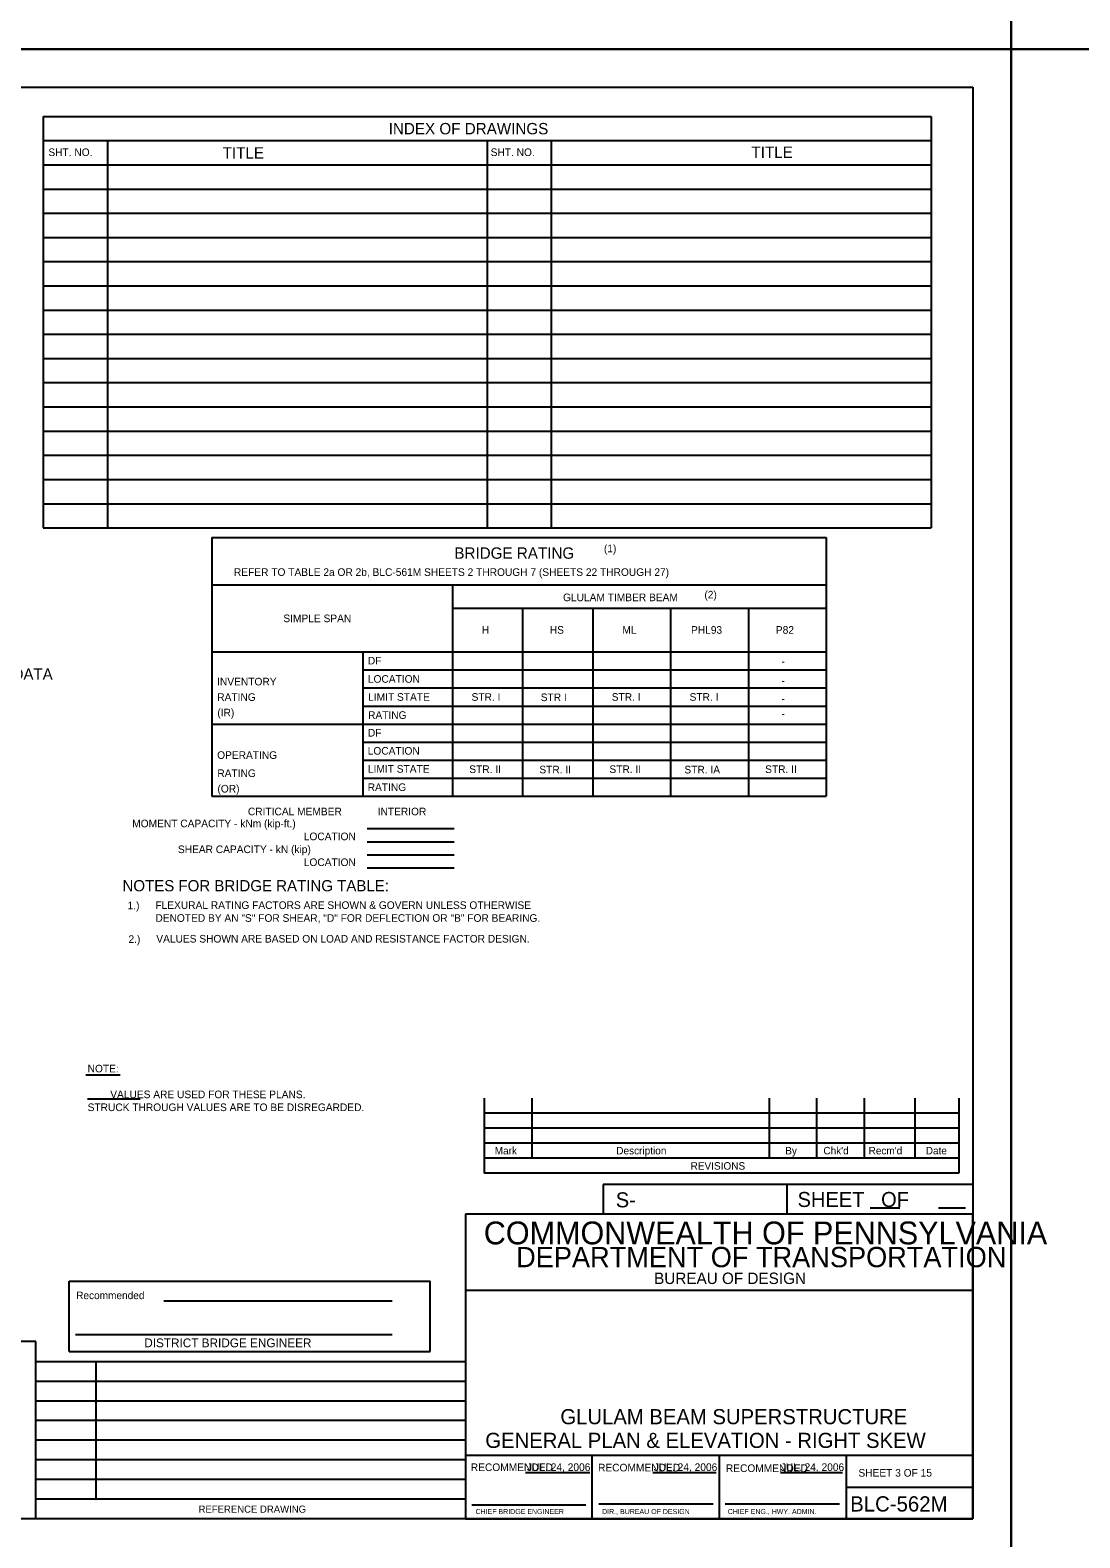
# Model space of a CAD drawing. Extents: x 638263 to 640360, y 293683 to 298655.
# Drawn here: x 638890 to 639304, y 296661 to 297255 of the extents above; entities that cross this region are included whole.
import ezdxf

# ---------------------------------------------------------------- set-up
doc = ezdxf.new("R2010")
doc.units = 0
for name, color, linetype in [('2', 7, 'Continuous'), ('4', 7, 'Continuous'), ('7', 7, 'Continuous'), ('PLT-BNDY', 7, 'Continuous')]:
    doc.layers.add(name, color=color, linetype=linetype)

msp = doc.modelspace()

# ---------------------------------------------------------------- linework, layer by layer
at = {"layer": '2'}
for p, q in [((638475.46, 297232.46), (639261.46, 297232.46)), ((639261.46, 297232.46), (639261.46, 296668.46)), ((638911.89, 296843.36), (638925.46, 296843.36)), ((638912.63, 296833.92), (638933.33, 296833.92)), ((639068.92, 296834.15), (639068.92, 296804.62)), ((639087.62, 296834.15), (639087.62, 296810.53)), ((639181.13, 296834.15), (639181.13, 296810.53)), ((639199.83, 296834.15), (639199.83, 296810.53)), ((639218.53, 296834.15), (639218.53, 296810.53)), ((639238.59, 296834.15), (639238.59, 296810.53)), ((639255.94, 296834.15), (639255.94, 296804.62)), ((639255.94, 296828.24), (639068.92, 296828.24)), ((639255.94, 296822.34), (639068.92, 296822.34)), ((639255.94, 296816.43), (639068.92, 296816.43)), ((639255.94, 296810.53), (639068.92, 296810.53)), ((639255.94, 296804.62), (639068.92, 296804.62)), ((639261.46, 296800.11), (639115.78, 296800.11)), ((639115.78, 296800.11), (639115.78, 296788.46)), ((639188.09, 296800.11), (639188.09, 296788.46)), ((639261.46, 296788.46), (639061.46, 296788.46)), ((639061.46, 296788.46), (639061.46, 296668.46)), ((639220.95, 296791), (639232.6, 296791)), ((639247.83, 296791), (639258.56, 296791)), ((639261.46, 296668.46), (639261.46, 296788.46)), ((638905.4, 296734.31), (638905.4, 296762.1)), ((638905.4, 296762.1), (639047.58, 296762.1)), ((639047.58, 296734.31), (639047.58, 296762.1)), ((639261.46, 296758.46), (639061.46, 296758.46)), ((638942.6, 296754.38), (639032.62, 296754.38)), ((638907.84, 296741.02), (639032.62, 296741.02)), ((638905.4, 296734.31), (639047.58, 296734.31)), ((639261.46, 296693.46), (639061.46, 296693.46)), ((639111.46, 296668.46), (639111.46, 296693.46)), ((639161.46, 296693.46), (639161.46, 296668.46)), ((639211.46, 296693.46), (639211.46, 296668.46)), ((639085.11, 296686.64), (639110.49, 296686.64)), ((639135.38, 296686.64), (639160.27, 296686.64)), ((639185.65, 296686.64), (639210.06, 296686.64)), ((639211.46, 296680.96), (639261.46, 296680.96)), ((639063.96, 296673.96), (639108.96, 296673.96)), ((639114.08, 296674.33), (639159.08, 296674.33)), ((639163.83, 296674.33), (639208.83, 296674.33)), ((639261.46, 296668.46), (638475.46, 296668.46)), ((639061.46, 296668.46), (639261.46, 296668.46))]:
    msp.add_line(p, q, dxfattribs=at)
at = {"layer": '4'}
for p, q in [((638895.05, 297220.97), (639245.05, 297220.97)), ((638895.05, 297220.97), (638895.05, 297058.86)), ((639245.05, 297220.97), (639245.05, 297058.86)), ((638895.05, 297211.44), (639070.05, 297211.44)), ((638920.52, 297211.44), (638920.52, 297058.86)), ((639070.05, 297211.44), (639245.05, 297211.44)), ((639070.05, 297211.44), (639070.05, 297058.86)), ((639095.21, 297211.44), (639095.21, 297058.86)), ((638895.05, 297201.9), (639070.05, 297201.9)), ((639070.05, 297201.9), (639245.05, 297201.9)), ((638895.05, 297192.36), (639070.05, 297192.36)), ((639070.05, 297192.36), (639245.05, 297192.36)), ((638895.05, 297182.83), (639070.05, 297182.83)), ((639070.05, 297182.83), (639245.05, 297182.83)), ((638895.05, 297173.29), (639070.05, 297173.29)), ((639070.05, 297173.29), (639245.05, 297173.29)), ((638895.05, 297163.76), (639070.05, 297163.76)), ((639070.05, 297163.76), (639245.05, 297163.76)), ((638895.05, 297154.22), (639070.05, 297154.22)), ((639070.05, 297154.22), (639245.05, 297154.22)), ((638895.05, 297144.68), (639070.05, 297144.68)), ((639070.05, 297144.68), (639245.05, 297144.68)), ((638895.05, 297135.15), (639070.05, 297135.15)), ((639070.05, 297135.15), (639245.05, 297135.15)), ((638895.05, 297125.61), (639070.05, 297125.61)), ((639070.05, 297125.61), (639245.05, 297125.61)), ((638895.05, 297116.08), (639070.05, 297116.08)), ((639070.05, 297116.08), (639245.05, 297116.08)), ((638895.05, 297106.54), (639070.05, 297106.54)), ((639070.05, 297106.54), (639245.05, 297106.54)), ((638895.05, 297097.01), (639070.05, 297097.01)), ((639070.05, 297097.01), (639245.05, 297097.01)), ((638895.05, 297087.47), (639070.05, 297087.47)), ((639070.05, 297087.47), (639245.05, 297087.47)), ((638895.05, 297077.93), (639070.05, 297077.93)), ((639070.05, 297077.93), (639245.05, 297077.93)), ((638895.05, 297068.4), (639070.05, 297068.4)), ((639070.05, 297068.4), (639245.05, 297068.4)), ((638895.05, 297058.86), (639245.05, 297058.86)), ((639021.04, 297002.91), (639203.67, 297002.91)), ((639021.04, 296995.8), (639203.67, 296995.8)), ((639021.04, 296988.68), (639203.67, 296988.68)), ((639021.04, 296974.45), (639203.67, 296974.45)), ((639021.04, 296967.33), (639203.67, 296967.33)), ((639021.04, 296960.22), (639203.67, 296960.22)), ((639022.83, 296940.43), (639057.1, 296940.43)), ((639022.83, 296935.11), (639057.1, 296935.11)), ((639022.83, 296930.06), (639057.1, 296930.06)), ((639022.83, 296924.88), (639057.1, 296924.88)), ((638892.25, 296738.31), (638754.05, 296738.31)), ((638892.25, 296668.46), (638892.25, 296738.31)), ((639061.46, 296730.34), (638892.25, 296730.34)), ((638915.96, 296676.19), (638915.96, 296730.34)), ((639061.46, 296722.6), (638892.25, 296722.6)), ((639061.46, 296714.87), (638892.25, 296714.87)), ((639061.46, 296707.13), (638892.25, 296707.13)), ((639061.46, 296699.4), (638892.25, 296699.4)), ((639061.46, 296691.66), (638892.25, 296691.66)), ((639061.46, 296683.93), (638892.25, 296683.93)), ((639061.46, 296676.19), (638892.25, 296676.19))]:
    msp.add_line(p, q, dxfattribs=at)
at = {"layer": '7'}
for p, q in [((638961.55, 297055.11), (638961.55, 296953.1)), ((638961.55, 297055.11), (639203.67, 297055.11)), ((639203.67, 297055.11), (639203.67, 296953.1)), ((638961.55, 297036.41), (639203.67, 297036.41)), ((639056.4, 297036.41), (639056.4, 296953.1)), ((639056.4, 297027.21), (639203.67, 297027.21)), ((639084.01, 297027.21), (639084.01, 296953.1)), ((639111.62, 297027.21), (639111.62, 296953.1)), ((639142.31, 297027.21), (639142.31, 296953.1)), ((639172.99, 297027.21), (639172.99, 296953.1)), ((638961.55, 297010.03), (639203.67, 297010.03)), ((639021.04, 297010.03), (639021.04, 296953.1)), ((638961.55, 296981.56), (639203.67, 296981.56)), ((638961.55, 296953.1), (639203.67, 296953.1))]:
    msp.add_line(p, q, dxfattribs=at)
at = {"layer": 'PLT-BNDY'}
for points in [[(638435.46, 297841.46), (639276.46, 297841.46), (639276.46, 297247.46), (638435.46, 297247.46)], [(639276.46, 297841.46), (640117.46, 297841.46), (640117.46, 297247.46), (639276.46, 297247.46)], [(638435.46, 297247.46), (639276.46, 297247.46), (639276.46, 296653.46), (638435.46, 296653.46)], [(639276.46, 297247.46), (640117.46, 297247.46), (640117.46, 296653.46), (639276.46, 296653.46)]]:
    msp.add_lwpolyline(points, close=True, dxfattribs=at)

# ---------------------------------------------------------------- texts
at = {"layer": '2'}
for s, height, p in [('MOMENT CAPACITY - kNm (kip-ft.)', 3, (638930.2, 296940.9)), ('LOCATION', 3, (638997.8, 296935.81)), ('SHEAR CAPACITY - kN (kip)', 3, (638948.2, 296930.73)), ('LOCATION', 3, (638997.8, 296925.64)), ('NOTE:', 3, (638912.63, 296844.34)), ('        VALUES ARE USED FOR THESE PLANS.  ', 3, (638912.63, 296834.17)), ('STRUCK THROUGH VALUES ARE TO BE DISREGARDED.', 3, (638912.63, 296829.09)), ('Mark', 2.952, (639073.02, 296812.03)), ('Description', 2.9523, (639120.92, 296812.03)), ('By', 2.952, (639187.49, 296812.03)), ("Chk'd", 2.952, (639202.52, 296812.03)), ("Recm'd", 2.953, (639220.33, 296812.03)), ('Date', 2.952, (639242.86, 296812.03)), ('REVISIONS', 2.952, (639150.2, 296806.01)), ('S-', 5.905, (639120.73, 296791.17)), ('COMMONWEALTH OF PENNSYLVANIA', 9, (639068.71, 296776.58)), ('DEPARTMENT OF TRANSPORTATION', 8.0002, (639081.46, 296767.58)), ('BUREAU OF DESIGN', 4.5, (639135.83, 296760.96)), ('Recommended', 2.9682, (638908.11, 296755)), ('GENERAL PLAN & ELEVATION - RIGHT SKEW', 5.9728, (639069.31, 296696.37)), ('RECOMMENDED', 3, (639063.61, 296687.27)), ('JUL. 24, 2006', 3, (639085.74, 296687.3)), ('RECOMMENDED', 3, (639113.74, 296687.14)), ('JUL. 24, 2006', 3, (639135.74, 296687.3)), ('RECOMMENDED', 3, (639164.11, 296686.89)), ('JUL. 24, 2006', 3, (639185.74, 296687.3)), ('SHEET 3 OF 15', 3, (639216.33, 296685.08)), ('BLC-562M', 6, (639213.08, 296671.33)), ('CHIEF BRIDGE ENGINEER', 2.0002, (639065.46, 296670.33)), ('DIR., BUREAU OF DESIGN', 2.0002, (639115.33, 296670.33)), ('CHIEF ENG., HWY. ADMIN.', 2.0002, (639164.83, 296670.33))]:
    msp.add_text(s, height=height, dxfattribs=at).set_placement(p)
for s, height, rotation, p in [('SHEET   OF', 5.907, 360, (639192.35, 296791.31)), ('DISTRICT BRIDGE ENGINEER', 3.4629, 359.99999, (638934.95, 296736.04))]:
    msp.add_text(s, height=height, rotation=rotation, dxfattribs=at).set_placement(p)
at = {"layer": '4'}
for s, height, p in [('INDEX OF DRAWINGS', 4.4792, (639031.26, 297213.91)), ('SHT. NO.', 3, (638897.16, 297205.36)), ('TITLE', 4.479, (638965.83, 297204.37)), ('SHT. NO.', 3, (639071.42, 297205.36)), ('TITLE', 4.479, (639174.17, 297204.63)), ('BRIDGE RATING', 4.4792, (639057.11, 297046.7)), ('(1)', 3, (639116.06, 297049.25)), ('REFER TO TABLE 2a OR 2b, BLC-561M SHEETS 2 THROUGH 7 (SHEETS 22 THROUGH 27)', 3, (638970.28, 297039.93)), ('GLULAM TIMBER BEAM', 3, (639099.95, 297029.98)), ('(2)', 3, (639155.64, 297031.05)), ('SIMPLE SPAN', 3, (638989.75, 297021.71)), ('H', 3, (639067.96, 297017.15)), ('HS', 3, (639094.73, 297017.15)), ('ML', 3, (639123.32, 297017.15)), ('PHL93', 3, (639150.37, 297017.15)), ('P82', 3, (639183.81, 297017.15)), ('DF', 3, (639023.05, 297005.04)), ('-', 3, (639186, 297004.82)), ('HYDRAULIC DATA', 4.4292, (638847.2, 296999.04)), ('LOCATION', 3, (639023.05, 296997.85)), ('INVENTORY', 3, (638963.66, 296996.8)), ('-', 3, (639186, 296997.21)), ('RATING', 3, (638963.7, 296990.7)), ('LIMIT STATE', 3, (639023.16, 296990.74)), ('STR. I', 3, (639063.91, 296990.74)), ('STR I', 3, (639091.15, 296990.61)), ('STR. I', 3, (639119.13, 296990.75)), ('STR. I', 3, (639149.81, 296990.75)), ('-', 3, (639186, 296990.1)), ('(IR)', 3, (638963.74, 296984.59)), ('RATING', 3, (639023.13, 296983.62)), ('-', 3, (639186, 296984.19)), ('DF', 3, (639023.05, 296976.63)), ('OPERATING', 3, (638963.67, 296967.85)), ('LOCATION', 3, (639022.98, 296969.52)), ('LIMIT STATE', 3, (639023.06, 296962.41)), ('STR. II', 3, (639063, 296962.28)), ('STR. II', 3, (639090.61, 296962.15)), ('STR. II', 3, (639118.22, 296962.29)), ('STR. IA', 3, (639147.77, 296962.12)), ('STR. II', 3, (639179.59, 296962.29)), ('RATING', 3, (638963.74, 296960.71)), ('(OR)', 3, (638963.78, 296954.6)), ('RATING', 3, (639022.98, 296955.2)), ('CRITICAL MEMBER', 3, (638975.78, 296945.62)), ('INTERIOR', 3, (639026.91, 296945.62)), ('NOTES FOR BRIDGE RATING TABLE:', 4.4292, (638926.37, 296915.67)), ('1.)', 3, (638928.38, 296908.59)), ('FLEXURAL RATING FACTORS ARE SHOWN & GOVERN UNLESS OTHERWISE', 3, (638939.33, 296908.73)), ('DENOTED BY AN "S" FOR SHEAR, "D" FOR DEFLECTION OR "B" FOR BEARING.', 3, (638939.33, 296903.66)), ('2.)', 3, (638928.74, 296895.35)), ('VALUES SHOWN ARE BASED ON LOAD AND RESISTANCE FACTOR DESIGN.', 3, (638939.69, 296895.49)), ('GLULAM BEAM SUPERSTRUCTURE', 5.9728, (639098.89, 296705.71))]:
    msp.add_text(s, height=height, dxfattribs=at).set_placement(p)
msp.add_text('REFERENCE DRAWING', height=2.8082, rotation=360, dxfattribs=at).set_placement((638956.34, 296670.86))

doc.saveas('drawing.dxf')
